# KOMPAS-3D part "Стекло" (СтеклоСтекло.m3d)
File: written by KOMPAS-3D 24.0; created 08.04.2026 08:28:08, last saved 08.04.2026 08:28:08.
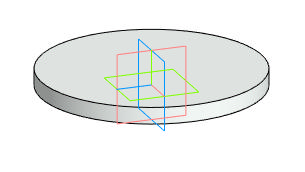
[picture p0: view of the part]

Document properties: Автор: Main; Полное имя файла: D:\DN.ru Аутсерс\Стекло смотровое DN.ru\Исходники\Стекло смотровое DN.ru SG2-34G-F тип В ГОСТ 21836-2021 Ду125 Ру16, углеродистая сталь, фланцевое\СтеклоСтекло.m3d

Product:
- Body: Твердое тело1  | qty 1
- Part/product: Стекло

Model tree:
1. Твердое тело1  (labels: Твердое тело1)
